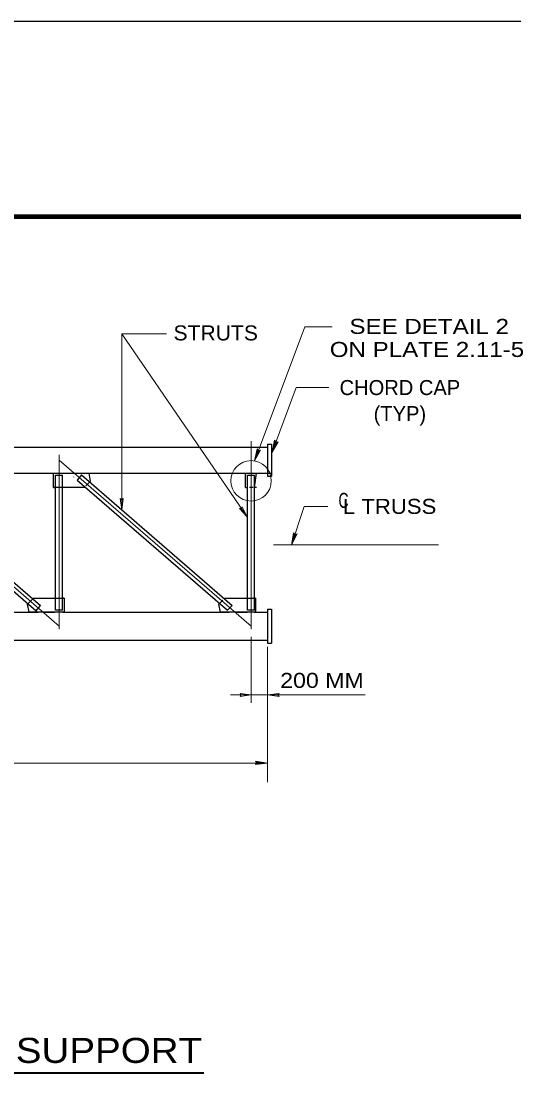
# Model space of a CAD drawing. Extents: x 312601.858 to 312602.699, y 144420.109 to 144420.704.
# Drawn here: x 312602.1325 to 312602.2309, y 144420.4937 to 144420.7035 of the extents above; entities that cross this region are included whole.
import ezdxf
from ezdxf.enums import TextEntityAlignment as Align

# ---------------------------------------------------------------- set-up
doc = ezdxf.new("R2010")
doc.units = 0
doc.header["$LTSCALE"] = 0.0012
doc.linetypes.add('DOT_DASHED', pattern=[7.7, 5, -1.2, 0.3, -1.2])
for name, color, linetype, lineweight in [('1', 7, 'Continuous', 13), ('2', 7, 'Continuous', 25), ('39', 7, 'Continuous', 13)]:
    doc.layers.add(name, color=color, linetype=linetype, lineweight=lineweight)

msp = doc.modelspace()

# ---------------------------------------------------------------- hatches: boundary and pattern name
at = {"layer": '39'}
for points in [[(312602.1834, 144420.6195), (312602.1838, 144420.6196), (312602.1826, 144420.6175), (312602.1831, 144420.6199)], [(312602.1799, 144420.6178), (312602.1803, 144420.6179), (312602.1791, 144420.6158), (312602.1796, 144420.6182)], [(312602.1872, 144420.6011), (312602.1876, 144420.6012), (312602.1865, 144420.599), (312602.1869, 144420.6014)], [(312602.1795, 144420.5555), (312602.1793, 144420.5559), (312602.1817, 144420.5555), (312602.1793, 144420.5552)]]:
    msp.add_hatch(color=256, dxfattribs=at).paths.add_polyline_path(points)

# ---------------------------------------------------------------- linework, layer by layer
at = {"layer": '1'}
for p, q in [((312602.1526, 144420.6411), (312602.1526, 144420.606)), ((312602.1526, 144420.6411), (312602.1615, 144420.6411)), ((312602.1826, 144420.6175), (312602.1874, 144420.6304)), ((312602.1874, 144420.6304), (312602.1939, 144420.6304)), ((312602.1829, 144420.599), (312602.2158, 144420.599)), ((312602.1784, 144420.5754), (312602.1784, 144420.5807)), ((312602.1784, 144420.5675), (312602.1784, 144420.5783)), ((312602.1817, 144420.5787), (312602.1817, 144420.5754)), ((312602.1817, 144420.5783), (312602.1817, 144420.5517)), ((312602.1743, 144420.5691), (312602.1784, 144420.5691)), ((312602.0054, 144420.5555), (312602.1817, 144420.5555))]:
    msp.add_line(p, q, dxfattribs=at)
at = {"layer": '1', "lineweight": 25}
for p, q in [((312602.0222, 144420.6185), (312602.1817, 144420.6185)), ((312602.1817, 144420.6191), (312602.1817, 144420.6127)), ((312602.1817, 144420.6191), (312602.1825, 144420.6191)), ((312602.1825, 144420.6191), (312602.1825, 144420.6127)), ((312602.1055, 144420.6119), (312602.1355, 144420.5859)), ((312602.106, 144420.6133), (312602.1394, 144420.6133)), ((312602.1064, 144420.613), (312602.1364, 144420.5869)), ((312602.139, 144420.6105), (312602.139, 144420.6133)), ((312602.139, 144420.6105), (312602.139, 144420.6133)), ((312602.139, 144420.6105), (312602.139, 144420.6133)), ((312602.1394, 144420.586), (312602.1394, 144420.6129)), ((312602.1394, 144420.6129), (312602.1408, 144420.6129)), ((312602.1406, 144420.6133), (312602.1444, 144420.6133)), ((312602.1408, 144420.6133), (312602.1427, 144420.6133)), ((312602.1408, 144420.586), (312602.1408, 144420.6129)), ((312602.1446, 144420.613), (312602.1437, 144420.6119)), ((312602.1437, 144420.6119), (312602.1737, 144420.586)), ((312602.1443, 144420.6133), (312602.1777, 144420.6133)), ((312602.1446, 144420.613), (312602.1746, 144420.5869)), ((312602.1772, 144420.6133), (312602.1794, 144420.6133)), ((312602.1773, 144420.6105), (312602.1773, 144420.6133)), ((312602.1777, 144420.586), (312602.1777, 144420.6129)), ((312602.1777, 144420.6129), (312602.1791, 144420.6129)), ((312602.1788, 144420.6133), (312602.1826, 144420.6133)), ((312602.179, 144420.6133), (312602.1809, 144420.6133)), ((312602.1791, 144420.6133), (312602.1817, 144420.6133)), ((312602.1791, 144420.586), (312602.1791, 144420.6129)), ((312602.1817, 144420.6127), (312602.1825, 144420.6127)), ((312602.139, 144420.6105), (312602.1394, 144420.6105)), ((312602.139, 144420.6105), (312602.1394, 144420.6105)), ((312602.139, 144420.6105), (312602.1394, 144420.6105)), ((312602.1451, 144420.6105), (312602.1407, 144420.6105)), ((312602.1451, 144420.6105), (312602.1407, 144420.6105)), ((312602.1451, 144420.6105), (312602.1407, 144420.6105)), ((312602.1452, 144420.6106), (312602.1451, 144420.6105)), ((312602.1773, 144420.6105), (312602.1777, 144420.6105)), ((312602.1788, 144420.6105), (312602.1781, 144420.6105)), ((312602.1348, 144420.5882), (312602.135, 144420.5884)), ((312602.135, 144420.5884), (312602.1394, 144420.5884)), ((312602.135, 144420.5884), (312602.1394, 144420.5884)), ((312602.135, 144420.5884), (312602.1394, 144420.5884)), ((312602.1411, 144420.5884), (312602.1407, 144420.5884)), ((312602.1411, 144420.5884), (312602.1407, 144420.5884)), ((312602.1411, 144420.5884), (312602.1408, 144420.5884)), ((312602.1411, 144420.5884), (312602.1411, 144420.5856)), ((312602.1411, 144420.5884), (312602.1411, 144420.5856)), ((312602.1411, 144420.5884), (312602.1411, 144420.5856)), ((312602.1731, 144420.5883), (312602.1732, 144420.5884)), ((312602.1732, 144420.5884), (312602.1777, 144420.5884)), ((312602.1732, 144420.5884), (312602.1776, 144420.5884)), ((312602.1732, 144420.5884), (312602.1776, 144420.5884)), ((312602.1793, 144420.5884), (312602.1789, 144420.5884)), ((312602.1793, 144420.5884), (312602.1789, 144420.5884)), ((312602.1793, 144420.5884), (312602.1791, 144420.5884)), ((312602.1793, 144420.5884), (312602.1793, 144420.5856)), ((312602.1793, 144420.5884), (312602.1793, 144420.5856)), ((312602.1793, 144420.5884), (312602.1793, 144420.5856)), ((312602.1355, 144420.5859), (312602.1364, 144420.5869)), ((312602.1737, 144420.586), (312602.1746, 144420.5869)), ((312602.1817, 144420.5862), (312602.1817, 144420.5794)), ((312602.1817, 144420.5862), (312602.1825, 144420.5862)), ((312602.1825, 144420.5862), (312602.1825, 144420.5794)), ((312602.1026, 144420.5856), (312602.1359, 144420.5856)), ((312602.1395, 144420.5856), (312602.1357, 144420.5856)), ((312602.1371, 144420.5856), (312602.1392, 144420.5856)), ((312602.1393, 144420.5856), (312602.1374, 144420.5856)), ((312602.1408, 144420.586), (312602.1394, 144420.586)), ((312602.1408, 144420.5856), (312602.174, 144420.5856)), ((312602.1777, 144420.5856), (312602.1739, 144420.5856)), ((312602.1754, 144420.5856), (312602.1777, 144420.5856)), ((312602.1756, 144420.5856), (312602.1777, 144420.5856)), ((312602.1791, 144420.586), (312602.1777, 144420.586)), ((312602.179, 144420.5856), (312602.1817, 144420.5856)), ((312602.0222, 144420.58), (312602.1817, 144420.58)), ((312602.1817, 144420.5794), (312602.1825, 144420.5794))]:
    msp.add_line(p, q, dxfattribs=at)
at = {"layer": '1', "linetype": 'DOT_DASHED'}
for p, q in [((312602.1784, 144420.5822), (312602.1784, 144420.6197)), ((312601.9933, 144420.6159), (312602.1862, 144420.6159)), ((312602.1019, 144420.6159), (312602.1401, 144420.5828)), ((312602.1401, 144420.5822), (312602.1401, 144420.617)), ((312602.1401, 144420.6159), (312602.1784, 144420.5828)), ((312601.9961, 144420.599), (312602.181, 144420.599))]:
    msp.add_line(p, q, dxfattribs=at)
at = {"layer": '1', "lineweight": 40}
msp.add_line((312601.9778, 144420.4937), (312602.169, 144420.4937), dxfattribs=at)
at = {"layer": '1'}
for points in [[(312602.1791, 144420.6157), (312602.1891, 144420.6425), (312602.1946, 144420.6425)], [(312602.1865, 144420.599), (312602.189, 144420.6067), (312602.1937, 144420.6067)], [(312602.1784, 144420.5691), (312602.1817, 144420.5691), (312602.2012, 144420.5691)]]:
    msp.add_lwpolyline(points, dxfattribs=at)
at = {"layer": '1', "lineweight": 25}
for points in [[(312602.1451, 144420.6105), (312602.1407, 144420.6105), (312602.1397, 144420.6105), (312602.139, 144420.6105), (312602.139, 144420.6133), (312602.146, 144420.6133), (312602.1463, 144420.6117)], [(312602.1463, 144420.6117), (312602.1462, 144420.6116), (312602.1454, 144420.6108)], [(312602.1795, 144420.6105), (312602.1791, 144420.6105), (312602.1795, 144420.6133)], [(312602.135, 144420.5884), (312602.1394, 144420.5884), (312602.1404, 144420.5884), (312602.1411, 144420.5884), (312602.1411, 144420.5856), (312602.1341, 144420.5856), (312602.1338, 144420.5872)], [(312602.1732, 144420.5884), (312602.1776, 144420.5884), (312602.1786, 144420.5884), (312602.1793, 144420.5884), (312602.1793, 144420.5856), (312602.1723, 144420.5856), (312602.172, 144420.5872)], [(312602.1338, 144420.5872), (312602.1339, 144420.5873), (312602.1347, 144420.5881)], [(312602.172, 144420.5872), (312602.1721, 144420.5873), (312602.1728, 144420.588)], [(312602.1753, 144420.5856), (312602.1774, 144420.5856), (312602.1756, 144420.5856)]]:
    msp.add_lwpolyline(points, dxfattribs=at)
at = {"layer": '1'}
for points in [[(312602.1529, 144420.6083), (312602.1526, 144420.606), (312602.1523, 144420.6083), (312602.1526, 144420.608)], [(312602.1766, 144420.6066), (312602.1776, 144420.6046), (312602.1761, 144420.6063), (312602.1765, 144420.6063)], [(312602.1762, 144420.5694), (312602.1784, 144420.5691), (312602.1762, 144420.5688), (312602.1764, 144420.5691)], [(312602.184, 144420.5688), (312602.1817, 144420.5691), (312602.184, 144420.5694), (312602.1837, 144420.5691)]]:
    msp.add_lwpolyline(points, close=True, dxfattribs=at)
at = {"layer": '1', "linetype": 'DOT_DASHED'}
msp.add_lwpolyline([(312602.0227, 144420.5828), (312602.0234, 144420.5828), (312602.1868, 144420.5828)], dxfattribs=at)
at = {"layer": '1'}
msp.add_circle((312602.1784, 144420.6118), 0.0040311, dxfattribs=at)
for centre, start, end in [((312602.14005, 144420.61301), 180, 180.74184), ((312602.140425, 144420.61281), 180, 180.74184), ((312602.143381, 144420.613125), 229.1584, 229.90024), ((312602.143648, 144420.612881), 229.1584, 229.90024), ((312602.143822, 144420.61297), 229.1584, 229.90024), ((312602.17825, 144420.61301), 180, 180.74184), ((312602.178625, 144420.61281), 180, 180.74184), ((312602.181581, 144420.613125), 229.1584, 229.90024), ((312602.181848, 144420.612881), 229.1584, 229.90024), ((312602.182022, 144420.61297), 229.1584, 229.90024), ((312602.139675, 144420.58609), 0, 0.74184), ((312602.178375, 144420.585895), 0, 0.74184)]:
    msp.add_arc(centre, 0.00068, start, end, dxfattribs=at)
at = {"layer": '2', "lineweight": 13}
msp.add_line((312602.1526, 144420.6411), (312602.1776, 144420.6046), dxfattribs=at)
at = {"layer": '39', "lineweight": 25}
msp.add_line((312601.8578, 144420.7035), (312602.6988, 144420.7035), dxfattribs=at)
at = {"layer": '39', "lineweight": 158}
msp.add_line((312601.9088, 144420.6645), (312602.6838, 144420.6645), dxfattribs=at)
at = {"layer": '39'}
for points in [[(312602.1834, 144420.6195), (312602.1838, 144420.6196), (312602.1826, 144420.6175), (312602.1831, 144420.6199)], [(312602.1799, 144420.6178), (312602.1803, 144420.6179), (312602.1791, 144420.6158), (312602.1796, 144420.6182)], [(312602.1872, 144420.6011), (312602.1876, 144420.6012), (312602.1865, 144420.599), (312602.1869, 144420.6014)], [(312602.1795, 144420.5555), (312602.1793, 144420.5559), (312602.1817, 144420.5555), (312602.1793, 144420.5552)]]:
    msp.add_lwpolyline(points, close=True, dxfattribs=at)

# ---------------------------------------------------------------- texts
at = {"layer": '2'}
for s, height, width, p in [('STRUTS', 0.003, 1.05, (312602.17135, 144420.6398)), ('SEE DETAIL 2', 0.003, 1.2, (312602.21395, 144420.6411)), ('ON PLATE 2.11-5', 0.003, 1.2, (312602.2135, 144420.6365)), ('C', 0.003, 0.7, (312602.19685, 144420.6064)), ('L TRUSS', 0.003, 1.1, (312602.20605, 144420.6052)), ('200 MM', 0.003, 1.15, (312602.19255, 144420.5705)), ('ELEVATION -TYPICAL CANTILEVER SIGN SUPPORT', 0.005, 1.15, (312602.07335, 144420.4957))]:
    msp.add_text(s, height=height, dxfattribs=dict(at, width=width)).set_placement(p, align=Align.CENTER)
for s, p in [('CHORD CAP', (312602.2081, 144420.6289)), ('(TYP)', (312602.2081, 144420.6237))]:
    msp.add_text(s, height=0.003, dxfattribs=at).set_placement(p, align=Align.CENTER)

doc.saveas('drawing.dxf')
